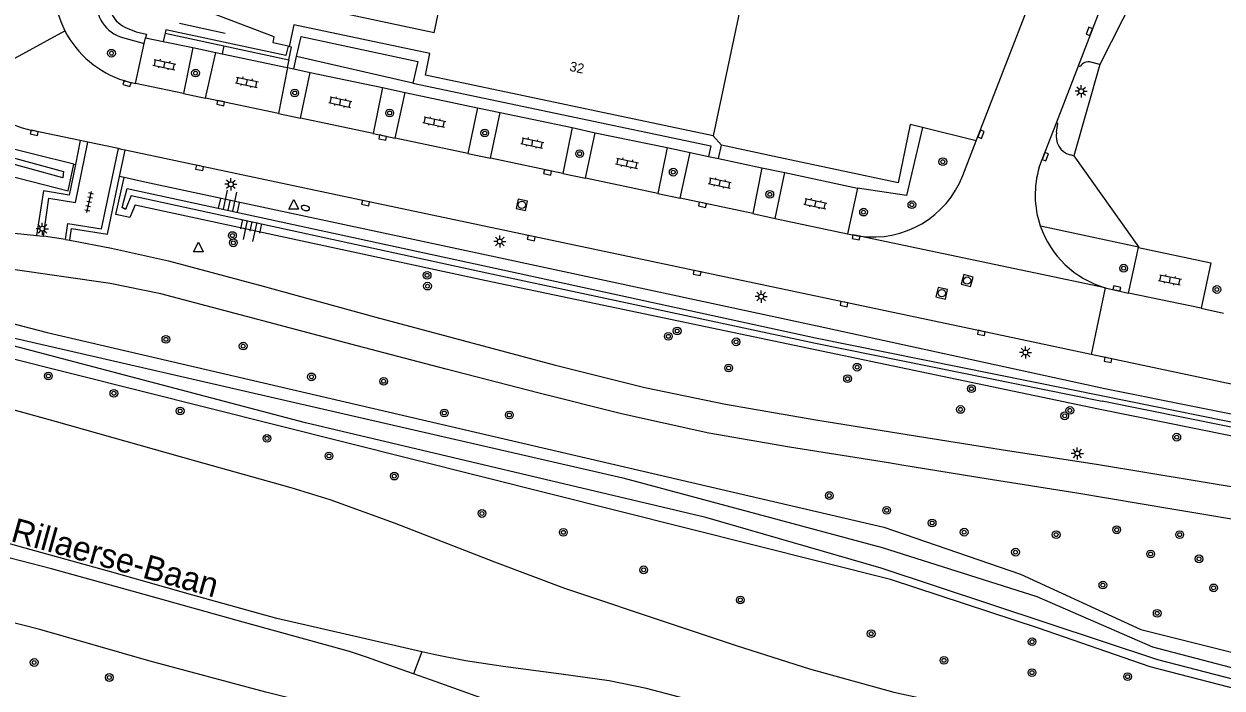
# Model space of a CAD drawing. Extents: x 131000 to 133013, y 393000 to 396501.
# Drawn here: x 131262.9 to 131386.6, y 393524.9 to 393593.5 of the extents above; entities that cross this region are included whole.
import ezdxf

# ---------------------------------------------------------------- set-up
doc = ezdxf.new("R2010")
doc.units = 0
for name, color, linetype in [('gg-afsc-muur', 7, 'Continuous'), ('gg-anno-huisnummerreeks BGT', 7, 'Continuous'), ('gg-anno-openbare ruimte label', 7, 'Continuous'), ('gg-bbg-hoofdgebouw', 7, 'Continuous'), ('gg-knt-BGT kruinlijn', 7, 'Continuous'), ('gg-knt-bovenkant onderkant talud', 7, 'Continuous'), ('gg-knt-verharding', 7, 'Continuous'), ('gg-kntw-bovenkant insteek waterloop', 7, 'Continuous'), ('gg-kntw-waterlijn', 7, 'Continuous'), ('gt-grn-groengrens', 7, 'Continuous'), ('gt-grn-vlakafsluiter', 7, 'Continuous'), ('gt-grn-weggrens', 7, 'Continuous'), ('gt-symb-boom', 7, 'Continuous'), ('gt-symb-brandkraan', 7, 'Continuous'), ('gt-symb-klinker verharding', 7, 'Continuous'), ('gt-symb-kolk', 7, 'Continuous'), ('gt-symb-lichtmast', 7, 'Continuous'), ('gt-symb-rioolschacht', 7, 'Continuous'), ('gt-symb-talud symbool', 7, 'Continuous'), ('gt-symb-tegel verharding', 7, 'Continuous'), ('gt-symb-waterafsluiter', 7, 'Continuous'), ('gx-grn-maaiveld', 7, 'Continuous')]:
    doc.layers.add(name, color=color, linetype=linetype)

# ---------------------------------------------------------------- blocks, each defined once
blk = doc.blocks.new('gt0-KOLK')
at = {"layer": 'gt-symb-kolk'}
blk.add_lwpolyline([(0, 0), (0.37, 0), (0.37, 0.4), (-0.38, 0.4), (-0.38, 0), (0, 0)], dxfattribs=at)
blk = doc.blocks.new('gt0-BOOM')
at = {"layer": 'gt-symb-boom'}
for radius in [0.4, 0.2]:
    blk.add_circle((0, 0), radius, dxfattribs=at)
blk = doc.blocks.new('gt0-KL1')
at = {"layer": 'gt-symb-klinker verharding'}
for p, q in [((-1.15, 0.3), (1.15, 0.3)), ((-1, -0.3), (-1, 0.3)), ((-0.5, 0.3), (-0.5, 0.45)), ((0, -0.3), (0, 0.3)), ((0.5, 0.3), (0.5, 0.45)), ((1, -0.3), (1, 0.3)), ((-1.15, -0.3), (1.15, -0.3)), ((-0.5, -0.45), (-0.5, -0.3)), ((0.5, -0.45), (0.5, -0.3))]:
    blk.add_line(p, q, dxfattribs=at)
blk = doc.blocks.new('gt0-LMAST')
at = {"layer": 'gt-symb-lichtmast'}
for p, q in [((-0.18, 0.17), (-0.45, 0.44)), ((-0.01, 0.25), (-0.01, 0.62)), ((0.17, 0.17), (0.44, 0.44)), ((-0.26, 0), (-0.63, 0)), ((-0.18, -0.18), (-0.45, -0.45)), ((-0.01, -0.25), (-0.01, -0.63)), ((0.44, -0.45), (0.17, -0.18)), ((0.24, 0), (0.62, 0))]:
    blk.add_line(p, q, dxfattribs=at)
blk.add_circle((-0.01, 0), 0.25, dxfattribs=at)
blk = doc.blocks.new('gt0-RS')
at = {"layer": 'gt-symb-rioolschacht'}
blk.add_lwpolyline([(-0.5, -0.5), (0.5, -0.5), (0.5, 0.5), (-0.5, 0.5)], close=True, dxfattribs=at)
blk.add_circle((0, 0), 0.375, dxfattribs=at)
blk = doc.blocks.new('gt0-WAFSL')
at = {"layer": 'gt-symb-waterafsluiter'}
for p, q in [((-0.5, -0.33), (0, 0.67)), ((0, 0.67), (0.5, -0.33)), ((0.5, -0.33), (-0.5, -0.33))]:
    blk.add_line(p, q, dxfattribs=at)
blk = doc.blocks.new('gt0-TALUD_1')
at = {"layer": 'gt-symb-talud symbool'}
for p, q in [((-1, -1), (-1, 0)), ((-0.5, -2), (-0.5, 0)), ((0, -1), (0, 0)), ((0.5, -2), (0.5, 0)), ((1, -1), (1, 0))]:
    blk.add_line(p, q, dxfattribs=at)
blk = doc.blocks.new('gt0-BR')
at = {"layer": 'gt-symb-brandkraan'}
for centre, radius, start, end in [((-0.24, 0), 0.206, 107.5669, 252.4331), ((0.6, -2.66), 3, 106.892, 107.5669), ((0, -0.69), 0.938, 73.108, 106.892), ((-0.6, -2.66), 3, 72.4331, 73.108), ((0.24, 0), 0.206, 287.567, 72.4331), ((0.6, 2.66), 3, 252.4331, 253.108), ((0, 0.69), 0.938, 253.108, 286.8921), ((-0.6, 2.66), 3, 286.8921, 287.567)]:
    blk.add_arc(centre, radius, start, end, dxfattribs=at)
blk = doc.blocks.new('gt0-TEG1')
at = {"layer": 'gt-symb-tegel verharding'}
for p, q in [((-1.12, 0), (1.12, 0)), ((-0.9, -0.25), (-0.9, 0.25)), ((-0.45, -0.25), (-0.45, 0.25)), ((0, -0.25), (0, 0.25)), ((0.45, -0.25), (0.45, 0.25)), ((0.9, -0.25), (0.9, 0.25))]:
    blk.add_line(p, q, dxfattribs=at)

msp = doc.modelspace()

# ---------------------------------------------------------------- linework, layer by layer
at = {"layer": 'gg-afsc-muur'}
for p, q in [((131278.99, 393593.54), (131283.71, 393592.5)), ((131277.49, 393592.52), (131283.56, 393591.21)), ((131283.56, 393591.21), (131290.26, 393589.77))]:
    msp.add_line(p, q, dxfattribs=at)
for points in [[(131290.2, 393591.16), (131289.98, 393590.19), (131277.56, 393592.86), (131277.49, 393592.52)], [(131290.26, 393589.77), (131290.54, 393591.08), (131290.31, 393591.14)]]:
    msp.add_lwpolyline(points, dxfattribs=at)
at = {"layer": 'gg-bbg-hoofdgebouw'}
msp.add_line((131290.2, 393591.16), (131290.31, 393591.14), dxfattribs=at)
for points in [[(131290.2, 393591.16), (131288.66, 393591.5), (131288.77, 393592.14), (131281.33, 393594.95), (131284.97, 393612.19)], [(131305.29, 393592.55), (131291.21, 393595.53), (131294.34, 393610.3), (131286.44, 393611.97), (131286.42, 393611.88), (131284.97, 393612.19)], [(131305.29, 393592.55), (131308.4, 393607.35), (131338.14, 393601.1), (131334.1, 393581.92)], [(131304.84, 393590.41), (131290.8, 393593.38), (131290.31, 393591.14)], [(131334.1, 393581.92), (131304.37, 393588.17), (131304.84, 393590.41)]]:
    msp.add_lwpolyline(points, dxfattribs=at)
at = {"layer": 'gg-knt-BGT kruinlijn'}
for points in [[(131274.01, 393575.77), (131273.4, 393574.32), (131273.06, 393574.51), (131273.59, 393576.48)], [(131273.59, 393576.48), (131310.79, 393568.43), (131344.66, 393561.07), (131374.33, 393555.09)], [(131274.01, 393575.77), (131310.71, 393567.77), (131344.64, 393560.52), (131374.25, 393554.51)], [(131374.33, 393555.09), (131472.61, 393535.15), (131555.31, 393517.46), (131619.8, 393503.35), (131707.97, 393484.7), (131731.97, 393480.17), (131732.98, 393480.67), (131735.96, 393480.06), (131735.85, 393479.74), (131732.9, 393480.11), (131732.07, 393479.5), (131707.92, 393484.23), (131619.67, 393502.99), (131555.2, 393516.93), (131472.56, 393534.7), (131374.25, 393554.51)]]:
    msp.add_lwpolyline(points, dxfattribs=at)
at = {"layer": 'gg-knt-bovenkant onderkant talud'}
for points in [[(131274.41, 393574.8), (131273.86, 393573.47), (131272.42, 393573.79), (131273.28, 393577.61)], [(131374.52, 393555.79), (131344.82, 393562.26), (131311.17, 393569.48), (131275.42, 393577.12), (131273.28, 393577.61)], [(131274.41, 393574.8), (131310.63, 393566.98), (131344.62, 393559.85), (131373.87, 393553.73)], [(131736.34, 393480.65), (131733.1, 393481.51), (131731.88, 393480.92), (131708.2, 393485.61), (131619.93, 393504.03), (131555.5, 393518.45), (131472.95, 393536.05), (131374.52, 393555.79)], [(131373.87, 393553.73), (131472.33, 393533.85), (131555.01, 393516.5), (131619.52, 393502.49), (131707.87, 393483.82), (131732.07, 393478.99), (131732.65, 393479.68), (131736.23, 393479.35), (131736.34, 393480.65)]]:
    msp.add_lwpolyline(points, dxfattribs=at)
at = {"layer": 'gg-knt-verharding'}
for p, q in [((131361.25, 393581.41), (131395.9, 393671.01)), ((131371.79, 393589.14), (131382.75, 393617.51)), ((131275.34, 393591.44), (131275.47, 393592.04)), ((131275.47, 393592.04), (131277.31, 393591.66)), ((131277.49, 393592.52), (131277.31, 393591.66)), ((131274.45, 393587.32), (131275.34, 393591.44)), ((131277.31, 393591.66), (131280.35, 393591.04)), ((131280.35, 393591.04), (131279.4, 393586.28)), ((131283.56, 393591.21), (131283.39, 393590.39)), ((131281.68, 393585.8), (131282.73, 393590.53)), ((131282.73, 393590.53), (131283.39, 393590.39)), ((131283.39, 393590.39), (131290.09, 393588.97)), ((131290.26, 393589.77), (131290.09, 393588.97)), ((131290.79, 393588.82), (131291.08, 393590.11)), ((131373.99, 393589.29), (131373.08, 393589.53)), ((131290.15, 393588.96), (131289.21, 393584.22)), ((131290.09, 393588.97), (131290.15, 393588.96)), ((131291.49, 393583.73), (131292.49, 393588.46)), ((131292.49, 393588.46), (131299.94, 393586.9)), ((131369.52, 393583.25), (131371.79, 393589.14)), ((131373.99, 393589.29), (131371.31, 393579.84)), ((131371.97, 393589.07), (131371.79, 393589.14)), ((131273.29, 393587.6), (131274.45, 393587.32)), ((131279.4, 393586.28), (131274.45, 393587.32)), ((131299.94, 393586.9), (131298.98, 393582.15)), ((131279.4, 393586.28), (131281.68, 393585.8)), ((131289.21, 393584.22), (131281.68, 393585.8)), ((131301.26, 393581.66), (131302.27, 393586.38)), ((131302.27, 393586.38), (131309.76, 393584.8)), ((131309.76, 393584.8), (131308.77, 393580.09)), ((131289.21, 393584.22), (131291.49, 393583.73)), ((131298.98, 393582.15), (131291.49, 393583.73)), ((131311.09, 393579.6), (131312.1, 393584.33)), ((131312.1, 393584.33), (131319.54, 393582.76)), ((131367.75, 393578.69), (131369.52, 393583.25)), ((131268.74, 393581.42), (131263.78, 393582.48)), ((131298.98, 393582.15), (131301.26, 393581.66)), ((131319.54, 393582.76), (131318.57, 393578.01)), ((131320.89, 393577.54), (131321.91, 393582.24)), ((131321.91, 393582.24), (131329.34, 393580.7)), ((131361.25, 393581.41), (131355.7, 393582.77)), ((131269.52, 393581.26), (131268.74, 393581.42)), ((131272.68, 393580.59), (131269.52, 393581.26)), ((131308.77, 393580.09), (131301.26, 393581.66)), ((131334.65, 393579.56), (131334.94, 393580.94)), ((131359.87, 393577.83), (131361.25, 393581.41)), ((131272.98, 393580.52), (131272.68, 393580.59)), ((131273.38, 393580.44), (131272.98, 393580.52)), ((131308.77, 393580.09), (131311.09, 393579.6)), ((131318.57, 393578.01), (131311.09, 393579.6)), ((131329.34, 393580.7), (131328.36, 393575.95)), ((131330.68, 393575.47), (131331.7, 393580.19)), ((131331.7, 393580.19), (131333.61, 393579.78)), ((131333.61, 393579.78), (131334.65, 393579.56)), ((131334.65, 393579.56), (131339.12, 393578.61)), ((131371.31, 393579.84), (131370.93, 393579.94)), ((131339.12, 393578.61), (131338.17, 393573.88)), ((131318.57, 393578.01), (131320.89, 393577.54)), ((131328.36, 393575.95), (131320.89, 393577.54)), ((131340.5, 393573.38), (131341.5, 393578.12)), ((131341.5, 393578.12), (131348.97, 393576.52)), ((131328.36, 393575.95), (131330.68, 393575.47)), ((131348.97, 393576.52), (131347.97, 393571.79)), ((131338.17, 393573.88), (131330.68, 393575.47)), ((131338.17, 393573.88), (131340.5, 393573.38)), ((131340.5, 393573.38), (131347.97, 393571.79)), ((131367.87, 393572.62), (131378.01, 393570.46)), ((131347.97, 393571.79), (131349.18, 393571.57)), ((131376.97, 393565.69), (131377.99, 393570.4)), ((131378.01, 393570.46), (131377.99, 393570.4)), ((131374.56, 393566.24), (131376.97, 393565.69)), ((131384.48, 393564.11), (131376.97, 393565.69)), ((131384.48, 393564.11), (131386.76, 393563.6))]:
    msp.add_line(p, q, dxfattribs=at)
for points in [[(131273.59, 393593.02), (131274.52, 393592.66), (131275.56, 393592.41), (131275.47, 393592.04)], [(131291.08, 393590.11), (131291.55, 393592.16), (131303.6, 393589.58), (131303.07, 393587.36)], [(131303.07, 393587.36), (131333.85, 393580.88), (131333.61, 393579.78)], [(131369.53, 393582.3), (131369.67, 393583.19), (131369.52, 393583.25)], [(131355.7, 393582.77), (131354.44, 393583.08), (131353.19, 393577.06), (131340.88, 393579.68)], [(131264.93, 393571.57), (131265.51, 393575.47), (131268.24, 393575.03), (131269.52, 393581.26)], [(131267.21, 393571.22), (131267.46, 393572.86), (131270.92, 393572.33), (131272.68, 393580.59)], [(131373.11, 393559.35), (131359.99, 393562.14), (131298.23, 393575.17), (131273.38, 393580.44)], [(131377.99, 393570.4), (131385.45, 393568.82), (131384.48, 393564.11)], [(131513.77, 393529.56), (131500.93, 393532.27), (131487.7, 393535.04), (131486.56, 393535.32), (131373.11, 393559.35)]]:
    msp.add_lwpolyline(points, dxfattribs=at)
for centre, radius, start, end in [((131276.37, 393597.49), 10.36, 161.655, 207.1621), ((131274.65, 393595.76), 2.94, 163.1015, 248.9529), ((131276.37, 393597.5), 10.36, 207.1778, 252.6728), ((131372.85, 393588.51), 1.04, 76.8736, 147.4003), ((131265.5, 393591.62), 9.3, 207.3234, 259.3245), ((131371.53, 393581.89), 2.04, 168.5137, 252.8902), ((131377.3, 393575.83), 9.97, 163.3369, 198.76), ((131350.57, 393581.45), 9.98, 261.9714, 338.7319), ((131377.31, 393575.83), 9.98, 198.7584, 253.9843)]:
    msp.add_arc(centre, radius, start, end, dxfattribs=at)
at = {"layer": 'gg-kntw-bovenkant insteek waterloop'}
for points in [[(131268.08, 393578.98), (131259.7, 393581.06), (131255.74, 393582.11)], [(131255.94, 393579.18), (131267.49, 393576.25), (131268.08, 393578.98)]]:
    msp.add_lwpolyline(points, dxfattribs=at)
at = {"layer": 'gg-kntw-waterlijn'}
msp.add_lwpolyline([(131242.97, 393582.9), (131242.79, 393583.39), (131243.19, 393583.61), (131247.08, 393582.57), (131251.15, 393582.17), (131255.84, 393581.26), (131267, 393578.23), (131266.93, 393577.57), (131255.66, 393580.67), (131251.03, 393581.45), (131246.76, 393581.75), (131242.97, 393582.9)], dxfattribs=at)
at = {"layer": 'gt-grn-groengrens'}
for p, q in [((131273.11, 393592.06), (131275.34, 393591.44)), ((131280.35, 393591.04), (131282.73, 393590.53)), ((131303.07, 393587.36), (131291.08, 393590.11)), ((131290.15, 393588.96), (131290.79, 393588.82)), ((131290.79, 393588.82), (131292.49, 393588.46)), ((131299.94, 393586.9), (131302.27, 393586.38)), ((131309.76, 393584.8), (131312.1, 393584.33)), ((131319.54, 393582.76), (131321.91, 393582.24)), ((131268.74, 393581.42), (131268.23, 393578.94)), ((131340.88, 393579.68), (131334.94, 393580.94)), ((131272.8, 393577.71), (131273.38, 393580.44)), ((131329.34, 393580.7), (131331.7, 393580.19)), ((131268.08, 393578.98), (131268.23, 393578.94)), ((131339.12, 393578.61), (131341.5, 393578.12)), ((131273.28, 393577.61), (131272.8, 393577.71)), ((131264.93, 393576.22), (131264.21, 393571.64))]:
    msp.add_line(p, q, dxfattribs=at)
for points in [[(131355.7, 393582.77), (131354.04, 393575.75), (131348.97, 393576.52)], [(131268.23, 393578.94), (131267.58, 393575.8), (131264.93, 393576.22)], [(131267.65, 393571.14), (131267.83, 393572.35), (131271.54, 393571.76), (131272.8, 393577.71)]]:
    msp.add_lwpolyline(points, dxfattribs=at)
msp.add_arc((131274.13, 393595.62), 3.71, 173.2353, 254.1317, dxfattribs=at)
at = {"layer": 'gt-grn-vlakafsluiter'}
for p, q in [((131386.24, 393613.31), (131373.99, 393589.29)), ((131334.94, 393580.94), (131334.1, 393581.92)), ((131371.31, 393579.84), (131378.01, 393570.46))]:
    msp.add_line(p, q, dxfattribs=at)
at = {"layer": 'gt-grn-weggrens'}
for p, q in [((131257.24, 393587.35), (131267.15, 393592.76)), ((131374.56, 393566.24), (131349.18, 393571.57)), ((131374.56, 393566.24), (131373.11, 393559.35))]:
    msp.add_line(p, q, dxfattribs=at)
at = {"layer": 'gx-grn-maaiveld'}
for p, q in [((131267.21, 393571.22), (131267.65, 393571.14)), ((131303.99, 393528.65), (131303.14, 393526.38))]:
    msp.add_line(p, q, dxfattribs=at)
for points in [[(131239.44, 393573.11), (131246.24, 393573.08), (131254.07, 393572.7), (131264.21, 393571.64)], [(131264.21, 393571.64), (131264.91, 393571.57), (131264.93, 393571.57)], [(131267.21, 393571.22), (131267.2, 393571.22), (131264.93, 393571.57)], [(131267.65, 393571.14), (131271.95, 393570.33), (131277.86, 393569.01), (131287.61, 393566.4), (131289.63, 393565.84), (131299.26, 393563.21), (131308.28, 393560.78), (131317.67, 393558.27), (131327.04, 393555.93), (131335.36, 393554.21), (131344.69, 393552.6), (131354.31, 393551.06), (131363.82, 393549.54), (131373.88, 393547.99), (131383.42, 393546.39), (131392.9, 393544.83), (131402.17, 393543.19), (131411.76, 393541.48), (131420.78, 393539.87), (131430.28, 393538.15)], [(131353.57, 393547.93), (131352.17, 393548.15), (131341.97, 393549.77), (131333.65, 393551.23), (131324.62, 393553.22), (131315.97, 393555.4), (131306.51, 393557.82), (131297.33, 393560.23), (131287.59, 393562.81), (131287.06, 393562.96), (131277.05, 393565.61), (131271.81, 393566.66), (131261.55, 393568.15), (131252.86, 393569.06), (131245.11, 393569.59), (131238.44, 393569.64), (131233.71, 393569.52), (131233.37, 393569.49), (131233.05, 393569.41), (131232.72, 393569.28)], [(131412.47, 393518.5), (131379.19, 393527.11), (131367.68, 393531.09), (131352.39, 393536.11), (131260.89, 393559.1), (131250.17, 393561.67), (131248.68, 393562.4), (131248.33, 393563.15), (131248.3, 393564.08), (131248.55, 393564.73), (131249.27, 393565.62), (131249.77, 393566.01), (131250.31, 393566.24), (131250.56, 393566.28), (131250.75, 393566.26), (131251.9, 393565.38), (131259.6, 393563.1), (131265.32, 393561.62), (131351.7, 393541.53)], [(131261.22, 393561.2), (131324.76, 393546.61), (131351.54, 393539.42), (131367.5, 393534.36), (131379.46, 393529.17), (131399.95, 393523.8), (131405.63, 393522.43), (131411.33, 393521.17), (131417.05, 393520.01), (131434.41, 393518.16), (131451.77, 393516.26), (131469.12, 393514.31), (131483.33, 393512.77), (131497.54, 393511.17), (131511.73, 393509.51), (131524.83, 393508.01), (131537.89, 393506.29), (131550.93, 393504.35), (131584.59, 393498.16)], [(131653.68, 393483.77), (131653.6, 393483.78), (131636.89, 393487.01), (131605.98, 393492.4), (131575.07, 393497.8), (131563.17, 393500.18), (131551.19, 393502.13), (131539.15, 393503.64), (131523.78, 393505.86), (131508.37, 393507.87), (131492.94, 393509.66), (131479.05, 393511.49), (131465.14, 393513.15), (131451.21, 393514.63), (131425.8, 393517.52), (131413.19, 393519.11), (131397.82, 393523.23), (131379.99, 393527.81), (131351.42, 393537.28), (131333.31, 393542.53), (131291.98, 393552.28), (131261.15, 393560.4)], [(131250.65, 393556.74), (131252.17, 393556.33), (131266.24, 393552.43), (131280.62, 393548.35), (131290.49, 393545.62), (131294.51, 393544.36), (131301.15, 393541.96), (131311.52, 393537.93), (131318.75, 393535.22), (131330.07, 393531.42), (131336.46, 393529.32), (131344.04, 393526.89), (131352.75, 393524.47), (131355.58, 393523.86)], [(131418.85, 393536.18), (131416.16, 393537.33), (131411.11, 393538.3), (131401.22, 393540.03), (131391.33, 393541.73), (131381.44, 393543.38), (131371.64, 393545.04), (131362.28, 393546.52), (131353.57, 393547.93)], [(131303.99, 393528.65), (131297.74, 393530.08), (131289.04, 393532.08), (131280.37, 393534.51), (131271.76, 393536.94), (131263.05, 393539.36), (131254.82, 393541.67), (131250.15, 393542.98)], [(131303.14, 393526.38), (131300.6, 393527.29), (131298.39, 393528.08), (131296.52, 393528.68), (131284.95, 393531.9), (131275.33, 393534.58), (131265.77, 393537.22), (131260.4, 393538.6), (131253.73, 393540.33), (131250.24, 393541.23)], [(131351.7, 393541.53), (131365.81, 393536.66), (131378.23, 393530.97), (131412.94, 393522.27)], [(131353.24, 393511.85), (131353.24, 393511.85), (131342.9, 393513.52), (131336.95, 393514.51), (131335.42, 393514.78), (131327.41, 393516.19), (131317.21, 393518.01), (131315.94, 393518.25), (131311.31, 393519.15), (131306.07, 393520.22), (131301.82, 393521.12), (131299.13, 393521.73), (131294.52, 393522.83), (131287.91, 393524.49), (131275.83, 393527.72), (131264.55, 393530.95), (131254.69, 393533.46), (131246.67, 393535.34), (131245.44, 393535.64)], [(131351.16, 393518.56), (131344.02, 393520.43), (131334.26, 393523), (131327.19, 393524.87), (131323.36, 393525.67), (131318.39, 393526.36), (131312.41, 393527.15), (131308.5, 393527.72), (131305.57, 393528.29), (131303.99, 393528.65)], [(131350.75, 393516.02), (131348.01, 393516.45), (131340.99, 393517.57), (131334.54, 393518.65), (131328.33, 393519.73), (131322.11, 393520.81), (131318.12, 393521.76), (131314.32, 393522.68), (131310.1, 393523.89), (131305.49, 393525.54), (131303.14, 393526.38)]]:
    msp.add_lwpolyline(points, dxfattribs=at)

# ---------------------------------------------------------------- block references
at = {"layer": 'gt-symb-boom'}
for p in [(131271.96, 393590.44), (131280.64, 393588.39), (131290.88, 393586.34), (131300.68, 393584.27), (131310.5, 393582.2), (131320.3, 393580.07), (131357.8, 393579.24), (131329.96, 393578.16), (131339.93, 393575.87), (131354.6, 393574.8), (131349.61, 393574.04), (131284.45, 393571.62), (131284.54, 393570.87), (131376.47, 393568.25), (131304.55, 393567.51), (131304.59, 393566.4), (131386.09, 393566.05), (131330.37, 393561.77), (131277.58, 393560.91), (131329.46, 393561.22), (131336.45, 393560.65), (131285.56, 393560.21), (131265.45, 393557.12), (131292.61, 393557.03), (131335.68, 393557.95), (131347.96, 393556.84), (131348.95, 393558.03), (131300.06, 393556.58), (131360.75, 393555.81), (131272.21, 393555.34), (131279.05, 393553.51), (131306.32, 393553.3), (131313.04, 393553.1), (131359.62, 393553.67), (131370.91, 393553.57), (131370.38, 393553.01), (131288.02, 393550.68), (131381.95, 393550.81), (131294.42, 393548.87), (131301.16, 393546.79), (131346.07, 393544.78), (131352, 393543.25), (131310.21, 393542.93), (131318.62, 393540.98), (131356.69, 393541.95), (131360, 393541), (131369.5, 393540.75), (131375.75, 393541.25), (131382.25, 393540.75), (131365.3, 393538.94), (131379.25, 393538.75), (131384.25, 393538.25), (131326.91, 393537.11), (131374.32, 393535.54), (131385.75, 393535.25), (131336.89, 393534.01), (131379.93, 393532.63), (131350.4, 393530.52), (131367.01, 393529.69), (131263.98, 393527.55), (131357.91, 393527.77), (131271.74, 393526), (131367, 393526.5), (131376.87, 393526.09)]:
    msp.add_blockref('gt0-BOOM', p, dxfattribs=at)
at = {"layer": 'gt-symb-brandkraan', "rotation": -14.119602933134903}
msp.add_blockref('gt0-BR', (131291.99, 393574.46), dxfattribs=at)
at = {"layer": 'gt-symb-klinker verharding'}
for p, rotation in [((131277.43, 393589.27), -12.062746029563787), ((131285.94, 393587.45), -12.062746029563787), ((131295.59, 393585.39), -12.118760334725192), ((131305.3, 393583.34), -12.062746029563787), ((131315.41, 393581.18), -12.062746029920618), ((131325.2, 393579.09), -12.062746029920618), ((131334.77, 393577.04), -12.062746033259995), ((131344.64, 393574.92), -12.062746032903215), ((131381.25, 393567.05), -11.714525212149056)]:
    msp.add_blockref('gt0-KL1', p, dxfattribs=dict(at, rotation=rotation))
at = {"layer": 'gt-symb-kolk'}
for p, rotation in [((131373.12, 393592.63), 68.84735479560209), ((131273.62, 393587.5), 162.83405393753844), ((131283.27, 393585.49), 167.99329169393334), ((131264.02, 393582.42), 168.04935273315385), ((131300, 393581.93), 168.17329607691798), ((131361.55, 393582.14), -111.28016631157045), ((131368.2, 393579.83), -111.04574081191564), ((131281.09, 393578.8), 167.881239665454), ((131317.02, 393578.34), 168.17329607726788), ((131298.23, 393575.17), 168.11724113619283), ((131333.01, 393574.99), 167.7571404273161), ((131315.34, 393571.56), 168.11724113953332), ((131348.87, 393571.63), 169.92566727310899), ((131332.46, 393567.95), 168.04935273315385), ((131375.72, 393565.97), -13.355340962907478), ((131347.63, 393564.74), 168.57767893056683), ((131361.81, 393561.76), 167.99329169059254), ((131374.89, 393558.98), 167.99329169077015)]:
    msp.add_blockref('gt0-KOLK', p, dxfattribs=dict(at, rotation=rotation))
at = {"layer": 'gt-symb-lichtmast'}
for p in [(131372.09, 393586.51), (131284.29, 393576.91), (131264.83, 393572.33), (131312.06, 393571), (131339.05, 393565.32), (131366.33, 393559.55), (131371.69, 393549.13)]:
    msp.add_blockref('gt0-LMAST', p, dxfattribs=at)
at = {"layer": 'gt-symb-rioolschacht'}
for p, rotation in [((131314.33, 393574.79), 168.40926316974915), ((131360.3, 393566.97), 164.86552497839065), ((131357.69, 393565.67), 166.22785457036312)]:
    msp.add_blockref('gt0-RS', p, dxfattribs=dict(at, rotation=rotation))
at = {"layer": 'gt-symb-talud symbool'}
for p, xscale, yscale, rotation in [((131283.97, 393574.24), 0.9997364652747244, 0.9997364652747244, 167.75714042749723), ((131286.5, 393573.06), 1.0003769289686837, 1.000376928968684, -12.410774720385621)]:
    msp.add_blockref('gt0-TALUD_1', p, dxfattribs=dict(at, xscale=xscale, yscale=yscale, rotation=rotation))
at = {"layer": 'gt-symb-tegel verharding', "rotation": 77.5209281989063}
msp.add_blockref('gt0-TEG1', (131269.66, 393575.08), dxfattribs=at)
at = {"layer": 'gt-symb-waterafsluiter'}
for p in [(131290.78, 393574.68), (131280.93, 393570.27)]:
    msp.add_blockref('gt0-WAFSL', p, dxfattribs=at)

# ---------------------------------------------------------------- texts
at = {"layer": 'gg-anno-huisnummerreeks BGT'}
msp.add_text('32', height=1, rotation=348.1, dxfattribs=at).set_placement((131319.19, 393588.63))
at = {"layer": 'gg-anno-openbare ruimte label'}
msp.add_text('Rillaerse-Baan', height=2.5, rotation=344.5, dxfattribs=at).set_placement((131261.45, 393540.1))

doc.saveas('drawing.dxf')
